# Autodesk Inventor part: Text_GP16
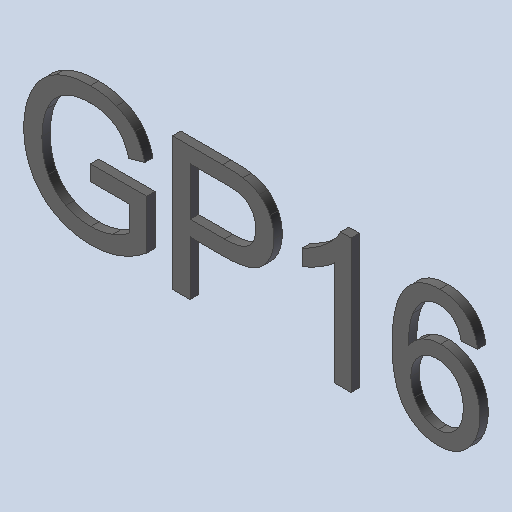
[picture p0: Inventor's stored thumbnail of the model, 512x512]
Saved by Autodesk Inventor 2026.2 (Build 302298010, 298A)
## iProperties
Created: 2026-10
Part Number: Text_GP16
Material: Générique
Document SubType Name: Modeling
Designer: mel
Density: 1 g/cm^3
Appearance: Par défaut
Author: mel
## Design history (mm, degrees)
feature "Base1"
feature "Base2"
feature "Base3"
feature "Base4"
node "Solide1"
node "Solide2"
node "Solide3"
node "Solide4"
